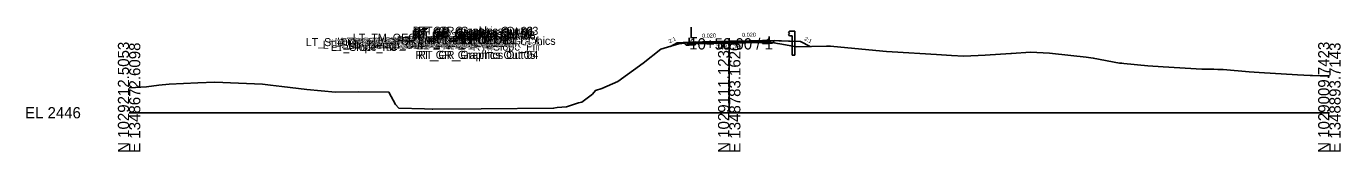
# Model space of a CAD drawing. Extents: x -26 to 1453, y -10 to 4527.
# Drawn here: x -25.7 to 302.8, y 490.3 to 521.5 of the extents above; entities that cross this region are included whole.
import ezdxf

# ---------------------------------------------------------------- set-up
doc = ezdxf.new("R2010")
doc.units = 0
for name, color, linetype in [('Default', 7, 'Continuous'), ('Exist CMT Pavement', 7, 'Continuous'), ('Exist Cross Section Cell', 7, 'Continuous'), ('Exist XS Center Line Elevation Label', 7, 'Continuous'), ('Exist XS Ground Line', 7, 'Continuous'), ('Prop CMT Guardrail Graphics', 7, 'Continuous'), ('Prop CMT Pvmt Course 1', 7, 'Continuous'), ('Prop CMT Pvmt Course 1 Wedge', 7, 'Continuous'), ('Prop CMT Pvmt Course 2', 7, 'Continuous'), ('Prop CMT Pvmt Course 3', 7, 'Continuous'), ('Prop CMT Pvmt Surface', 7, 'Continuous'), ('Prop CMT Pvmt Surface Shoulder', 7, 'Continuous'), ('Prop CMT Pvmt Wedge Surface 1', 7, 'Continuous'), ('Prop CMT Pvmt Wedge Surface 2', 7, 'Continuous'), ('Prop CMT Pvmt Wedge Surface 3', 7, 'Continuous'), ('Prop CMT Shld Paved Course 1', 7, 'Continuous'), ('Prop CMT Shld Paved Course 2', 7, 'Continuous'), ('Prop CMT Shld Paved Course 3', 7, 'Continuous'), ('Prop CMT Slope Grass', 7, 'Continuous'), ('Prop CMT Subgrade Earthwork', 7, 'Continuous'), ('Prop XS Earthwork Shape', 7, 'Continuous'), ('Prop XS EOT Tick Mark', 7, 'Continuous'), ('Prop XS SE Text', 7, 'Continuous'), ('Prop XS Side Slope Text', 7, 'Continuous')]:
    doc.layers.add(name, color=color, linetype=linetype)

msp = doc.modelspace()

# ---------------------------------------------------------------- linework, layer by layer
at = {"layer": 'Exist CMT Pavement'}
for points in [[(150, 517.75), (149.85, 517.75), (149.05, 517.74), (146.2, 517.68), (145.74, 517.67), (142.43, 517.61), (141.49, 517.59)], [(150, 517.75), (150.93, 517.76), (154.18, 517.77), (155.2, 517.78), (157.43, 517.79), (157.97, 517.79), (158.36, 517.79)]]:
    msp.add_lwpolyline(points, dxfattribs=at)
at = {"layer": 'Exist Cross Section Cell'}
for p, q in [((150, 500), (150, 518.56)), ((0, 500), (150, 500)), ((150, 500), (300, 500))]:
    msp.add_line(p, q, dxfattribs=at)
at = {"layer": 'Exist XS Ground Line'}
msp.add_lwpolyline([(0, 506.18), (0.2, 506.19), (4.35, 506.44), (7.42, 506.87), (10.03, 507.15), (17.18, 507.43), (21.41, 507.61), (27.32, 507.34), (33.36, 507.11), (35.34, 506.89), (38.16, 506.53), (44.46, 505.78), (51.56, 505.15), (57.36, 505.18), (64.93, 505.12), (66.55, 502.07), (67.45, 501.1), (73.86, 500.95), (75.74, 500.89), (75.95, 500.87), (88.02, 500.98), (106.1, 501.13), (107.01, 501.29), (109.37, 501.44), (112.31, 502.5), (113.13, 502.67), (115.83, 504.65), (116.56, 505.53), (118.14, 506.02), (122.14, 507.75), (128.49, 512.34), (132.91, 515.8), (135.39, 516.56), (137.41, 517.14), (139.58, 517.41), (140.98, 517.58), (146.2, 517.68), (149.85, 517.75), (150, 517.75), (155.2, 517.78), (157.97, 517.79), (158.68, 517.8), (159.05, 517.8), (159.36, 517.8), (159.51, 517.78), (160.7, 517.53), (162.08, 517.26), (162.61, 517.17), (166.85, 516.42), (174.28, 516.56), (175.31, 516.57), (188.43, 515.34), (189.34, 515.25), (190.74, 515.15), (201.77, 514.5), (205.57, 514.28), (208.64, 514.08), (213.96, 514.3), (220.38, 514.76), (220.44, 514.77), (220.53, 514.77), (225.3, 515.09), (230.03, 514.86), (230.83, 514.76), (239.25, 513.81), (241, 513.6), (247.59, 512.33), (248.16, 512.32), (248.62, 512.28), (254.59, 511.67), (258.47, 511.43), (268.14, 510.89), (271.15, 510.82), (272.13, 510.81), (273.46, 510.76), (279.93, 510.18), (282.48, 510), (292.06, 509.47), (295.23, 509.29), (295.76, 509.25), (297.69, 509.23), (300, 509.2)], dxfattribs=at)
at = {"layer": 'Prop CMT Guardrail Graphics'}
for points in [[(166.41, 520.33), (165.08, 520.33), (164.81, 520.04)], [(164.81, 520.04), (165.08, 519.75)], [(165.08, 519.75), (164.81, 519.45)], [(164.81, 519.45), (165.08, 519.16), (165.74, 519.16)], [(165.74, 519.16), (165.74, 514.33)], [(166.41, 514.33), (166.41, 520.33)], [(165.74, 514.33), (166.41, 514.33)]]:
    msp.add_lwpolyline(points, dxfattribs=at)
at = {"layer": 'Prop CMT Pvmt Course 1'}
for points in [[(150, 517.82), (140, 517.62)], [(140, 517.62), (140, 517.37)], [(140, 517.37), (141.48, 517.4)], [(141.48, 517.53), (150, 517.7)], [(141.48, 517.4), (141.48, 517.53)], [(150, 517.82), (160, 518.02)], [(158.36, 517.86), (150, 517.7)], [(150, 517.7), (150, 517.82)], [(150, 517.7), (150, 517.82)], [(158.36, 517.74), (158.36, 517.86)], [(160, 517.77), (158.36, 517.74)], [(160, 518.02), (160, 517.77)]]:
    msp.add_lwpolyline(points, dxfattribs=at)
at = {"layer": 'Prop CMT Pvmt Course 1 Wedge'}
for points in [[(153.82, 517.77), (155.2, 517.8)], [(158.36, 517.79), (157.97, 517.79), (155.2, 517.78), (153.82, 517.77)], [(155.2, 517.8), (157.97, 517.86), (158.36, 517.86)], [(158.36, 517.86), (158.36, 517.79)]]:
    msp.add_lwpolyline(points, dxfattribs=at)
at = {"layer": 'Prop CMT Pvmt Course 2'}
for points in [[(141.48, 517.4), (140, 517.37)], [(140, 517.37), (140, 517.12)], [(140, 517.12), (141.48, 517.15)], [(141.48, 517.15), (141.48, 517.4)], [(158.36, 517.74), (160, 517.77)], [(158.36, 517.49), (158.36, 517.74)], [(160, 517.52), (158.36, 517.49)], [(160, 517.77), (160, 517.52)]]:
    msp.add_lwpolyline(points, dxfattribs=at)
at = {"layer": 'Prop CMT Pvmt Course 3'}
for points in [[(141.48, 517.15), (140, 517.12)], [(140, 517.12), (140, 516.87)], [(140, 516.87), (141.48, 516.9)], [(141.48, 516.9), (141.48, 517.15)], [(158.36, 517.49), (160, 517.52)], [(158.36, 517.24), (158.36, 517.49)], [(160, 517.27), (158.36, 517.24)], [(160, 517.52), (160, 517.27)]]:
    msp.add_lwpolyline(points, dxfattribs=at)
at = {"layer": 'Prop CMT Pvmt Surface'}
for points in [[(150, 517.82), (140, 517.62)], [(150, 517.82), (160, 518.02)]]:
    msp.add_lwpolyline(points, dxfattribs=at)
at = {"layer": 'Prop CMT Pvmt Surface Shoulder'}
for points in [[(140, 517.62), (140, 517.62)], [(160, 518.02), (160, 518.02)]]:
    msp.add_lwpolyline(points, dxfattribs=at)
at = {"layer": 'Prop CMT Pvmt Wedge Surface 1'}
for points in [[(141.48, 517.65), (140, 517.62)], [(150, 517.7), (141.48, 517.53)], [(141.48, 517.53), (141.48, 517.65)], [(150, 517.7), (158.36, 517.86)], [(158.36, 517.99), (160, 518.02)], [(158.36, 517.86), (158.36, 517.99)]]:
    msp.add_lwpolyline(points, dxfattribs=at)
at = {"layer": 'Prop CMT Pvmt Wedge Surface 2'}
for points in [[(140, 517.37), (140, 517.62)], [(150, 517.57), (141.48, 517.4), (140, 517.37)], [(150, 517.57), (158.36, 517.74), (160, 517.77)], [(160, 517.77), (160, 518.02)]]:
    msp.add_lwpolyline(points, dxfattribs=at)
at = {"layer": 'Prop CMT Pvmt Wedge Surface 3'}
for points in [[(140, 517.12), (140, 517.62)], [(150, 517.32), (141.48, 517.15), (140, 517.12)], [(150, 517.32), (158.36, 517.49), (160, 517.52)], [(160, 517.52), (160, 518.02)]]:
    msp.add_lwpolyline(points, dxfattribs=at)
at = {"layer": 'Prop CMT Shld Paved Course 1'}
for points in [[(140, 517.62), (140, 517.62), (139.74, 517.37)], [(139.74, 517.37), (140, 517.37)], [(140, 517.37), (140, 517.62)], [(160, 518.02), (160, 518.02), (160.25, 517.78)], [(160, 517.77), (160, 518.02)], [(160.25, 517.78), (160, 517.77)]]:
    msp.add_lwpolyline(points, dxfattribs=at)
at = {"layer": 'Prop CMT Shld Paved Course 2'}
for points in [[(140, 517.37), (139.74, 517.37), (139.49, 517.11)], [(139.49, 517.11), (140, 517.12)], [(140, 517.12), (140, 517.37)], [(160, 517.77), (160.25, 517.78), (160.49, 517.53)], [(160, 517.52), (160, 517.77)], [(160.49, 517.53), (160, 517.52)]]:
    msp.add_lwpolyline(points, dxfattribs=at)
at = {"layer": 'Prop CMT Shld Paved Course 3'}
for points in [[(139.49, 517.11), (139.23, 516.86)], [(139.23, 516.86), (140, 516.87)], [(140, 517.12), (139.49, 517.11)], [(139.49, 517.11), (139.49, 517.11)], [(140, 516.87), (140, 517.12)], [(160, 517.52), (160.49, 517.53)], [(160, 517.27), (160, 517.52)], [(160.74, 517.29), (160, 517.27)], [(160.49, 517.53), (160.49, 517.53)], [(160.49, 517.53), (160.74, 517.29)]]:
    msp.add_lwpolyline(points, dxfattribs=at)
at = {"layer": 'Prop CMT Slope Grass'}
for points in [[(137, 517.38), (135.31, 516.54)], [(140, 517.62), (137, 517.38)], [(160, 518.02), (164.81, 517.83)], [(160, 518.02), (167.81, 517.71)], [(164.81, 517.83), (167.81, 517.71)], [(167.81, 517.71), (170.25, 516.49)]]:
    msp.add_lwpolyline(points, dxfattribs=at)
at = {"layer": 'Prop CMT Subgrade Earthwork'}
for points in [[(139.23, 516.86), (138.58, 517.51)], [(140, 516.87), (139.23, 516.86)], [(141.48, 516.9), (140, 516.87)], [(141.48, 516.9), (141.49, 517.59)], [(158.36, 517.24), (158.36, 517.79)], [(158.36, 517.24), (160, 517.27)], [(160, 517.27), (160.74, 517.29)], [(160.74, 517.29), (161.42, 517.97)]]:
    msp.add_lwpolyline(points, dxfattribs=at)
at = {"layer": 'Prop XS Earthwork Shape'}
for points in [[(137, 517.38), (135.31, 516.54), (135.39, 516.56), (137.41, 517.14), (138.78, 517.31), (138.58, 517.51)], [(137, 517.38), (135.31, 516.54), (135.39, 516.56), (137.41, 517.14), (138.78, 517.31), (138.58, 517.51)], [(140, 516.87), (139.23, 516.86), (138.78, 517.31), (139.58, 517.41), (140.98, 517.58), (141.49, 517.59), (141.48, 516.9)], [(140, 516.87), (139.23, 516.86), (138.78, 517.31), (139.58, 517.41), (140.98, 517.58), (141.49, 517.59), (141.48, 516.9)], [(158.36, 517.24), (158.36, 517.79), (158.68, 517.8), (159.05, 517.8), (159.36, 517.8), (159.51, 517.78), (160.7, 517.53), (160.93, 517.48), (160.74, 517.29), (160, 517.27)], [(158.36, 517.24), (158.36, 517.79), (158.68, 517.8), (159.05, 517.8), (159.36, 517.8), (159.51, 517.78), (160.7, 517.53), (160.93, 517.48), (160.74, 517.29), (160, 517.27)], [(164.81, 517.83), (167.81, 517.71), (170.25, 516.49), (166.85, 516.42), (162.61, 517.17), (162.08, 517.26), (160.93, 517.48), (161.42, 517.97)], [(164.81, 517.83), (167.81, 517.71), (170.25, 516.49), (166.85, 516.42), (162.61, 517.17), (162.08, 517.26), (160.93, 517.48), (161.42, 517.97)]]:
    msp.add_lwpolyline(points, close=True, dxfattribs=at)
at = {"layer": 'Prop XS EOT Tick Mark'}
for points in [[(140, 517.62), (140, 518.62)], [(160, 518.02), (160, 519.02)]]:
    msp.add_lwpolyline(points, dxfattribs=at)

# ---------------------------------------------------------------- texts
at = {"layer": 'Default'}
for s, height, p in [('LT_TM_OEOT', 2, (55.94, 517.7)), ('RT_Sub_Trench_Out_DLT', 2, (66.93, 517.04)), ('RT_PV1_OEEOP_Null', 2, (69.77, 517.07)), ('RT_GR_Graphics Out 08', 2, (70.66, 518.53)), ('RT_GR_Graphics Out 02', 2, (70.93, 519.41)), ('RT_GR_Graphics Out 09', 2, (70.93, 518.83)), ('RT_GR_Graphics Out 07', 2, (70.93, 518.24)), ('RT_GR_Graphics Out 01', 2, (71.22, 519.12)), ('RT_GR_Graphics Out 06', 2, (71.55, 518.24)), ('RT_GR_Graphics Out 03', 2, (72.26, 519.41)), ('RT_PV1_OEOT', 2, (75.69, 517.1)), ('RT_PS1_OEOP', 2, (75.76, 517.1)), ('RT_TM_OEOT', 2, (75.9, 518.1)), ('LT_Sub_Trench_Out_DLT', 2, (44.15, 516.59)), ('LT_Sub_Trench_Out', 2, (48.44, 515.94)), ('LT_Slope_Fill', 2, (50.43, 515.41)), ('LT_PS3_Shelf_Out', 2, (50.47, 516.19)), ('LT_GS_OS_CTL', 2, (51.37, 516.46)), ('LT_PV_Sub_Tie_Out', 2, (51.43, 516.59)), ('LT_PV1_OEEOP_Null', 2, (52.94, 516.73)), ('LT_PV_EG_TestPt3', 2, (52.94, 516.61)), ('LT_PV_OEEOP_EG', 2, (54.03, 516.59)), ('LT_PV1_OEEOP_W', 2, (54.47, 516.61)), ('LT_PS3_OEOP', 2, (54.73, 516.19)), ('LT_PS2_OEOP', 2, (54.98, 516.45)), ('LT_Sub_OEOT', 2, (55.08, 515.95)), ('LT_PV2_OEOT', 2, (55.17, 516.45)), ('LT_PV3_OEOT', 2, (55.17, 516.2)), ('LT_Sub_OEEOP', 2, (55.7, 515.98)), ('LT_PV1_OEOT', 2, (55.74, 516.7)), ('LT_PV2_OEEOP', 2, (55.79, 516.48)), ('LT_PV3_OEEOP', 2, (55.79, 516.23)), ('LT_PS1_OEOP', 2, (55.8, 516.7)), ('LT_PV_EG_TestPt2', 2, (56.25, 516.67)), ('LT_PV_EG_TestPt1', 2, (60.13, 516.74)), ('RT_PV_EG_TestPt1', 2, (61.96, 516.76)), ('RT_PV_EG_TestPt2', 2, (64.65, 516.77)), ('PV_EPGL_EG', 2, (66.24, 516.75)), ('PV2_PGL_W', 2, (67.02, 516.65)), ('PV3_PGL_W', 2, (67.02, 516.4)), ('RT_GS_OS_GR_Face_Graphics', 2, (67.22, 516.91)), ('PV1_PGL_W', 2, (67.58, 516.78)), ('RT_PV_EG_TestPt3', 2, (67.9, 516.79)), ('RT_PV_Sub_Tie_Out', 2, (68.26, 516.79)), ('PV1_PGL', 2, (69.47, 516.9)), ('RT_Sub_Trench_Out', 2, (69.89, 516.37)), ('RT_PV_OEEOP_EG', 2, (70.86, 516.79)), ('RT_PV1_OEEOP_W', 2, (71.3, 516.94)), ('RT_PS3_Shelf_Out', 2, (71.43, 516.61)), ('RT_Sub_OEEOP', 2, (72.53, 516.32)), ('RT_PV2_OEEOP', 2, (72.62, 516.82)), ('RT_PV3_OEEOP', 2, (72.62, 516.57)), ('RT_Sub_OEOT', 2, (75.03, 516.35)), ('RT_PV2_OEOT', 2, (75.13, 516.85)), ('RT_PV3_OEOT', 2, (75.13, 516.6)), ('RT_PS2_OEOP', 2, (75.44, 516.86)), ('RT_PS3_OEOP', 2, (75.68, 516.61)), ('RT_GS_OS_CTL', 2, (82.13, 516.79)), ('RT_Slope_Fill', 2, (85.88, 515.49)), ('RT_GR_Graphics Out 05', 2, (71.59, 513.41)), ('RT_GR_Graphics Out 04', 2, (72.26, 513.41)), ('-', 0.0001, (0, 500)), ('-', 0.0001, (0, 500)), ('-', 0.0001, (0, 500)), ('-', 0.0001, (0, 500))]:
    msp.add_text(s, height=height, dxfattribs=at).set_placement(p)
at = {"layer": 'Exist Cross Section Cell'}
for s, p in [('L', (140, 518.56)), ('10+50.00 / 1', (140, 515.76)), ('EL 2446', (-26, 498.6))]:
    msp.add_text(s, height=2.8, dxfattribs=at).set_placement(p)
for s, p in [('N 1029212.5053', (0, 490)), ('E 1348672.6098', (2.8, 490)), ('N 1029111.1238', (150, 490)), ('E 1348783.1620', (152.8, 490)), ('N 1029009.7423', (300, 490)), ('E 1348893.7143', (302.8, 490))]:
    msp.add_text(s, height=2.8, rotation=90, dxfattribs=at).set_placement(p)
at = {"layer": 'Exist XS Center Line Elevation Label'}
msp.add_text('2463.75', height=1.23, dxfattribs=at).set_placement((146.76, 515.73))
at = {"layer": 'Prop XS SE Text'}
for p in [(143.23, 518.69), (153.23, 518.89)]:
    msp.add_text('0.020', height=1, rotation=1.1458, dxfattribs=at).set_placement(p)
at = {"layer": 'Prop XS Side Slope Text'}
for rotation, p in [(26.5651, (135.11, 517.28)), (333.4349, (168.66, 518.12))]:
    msp.add_text('2:1', height=1, rotation=rotation, dxfattribs=at).set_placement(p)

doc.saveas('drawing.dxf')
